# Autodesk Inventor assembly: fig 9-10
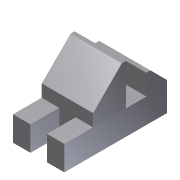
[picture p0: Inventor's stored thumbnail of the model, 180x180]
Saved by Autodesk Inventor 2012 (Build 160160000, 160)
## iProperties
Shininess: 64.0
Length Units: 11269
Angle Units: 11279
Time Units: 11290
Mass Units: 11283
Length Display Precision: 3
Angle Display Precision: 2
Created: 2002-01
Part Number: fig 9-10
Document SubType Name: Assembly
Designer: ***
Density: 0.0
Volumn: 0.0
Area: 0.0
PropertySet Name: Model Information
Control State: 0
Master: False
Checked Out: False
Author: ***
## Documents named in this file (3)
- C:\Users\CadCim\Documents\SAILESH\inventor-2011-fact-prt\c09_inv_2011-prt\c09_inv_2012_prt\fig 9-10.iam
- C:\Users\CadCim\Documents\SAILESH\inventor-2011-fact-prt\c09_inv_2011-prt\c09_inv_2012_prt\Part3.ipt
- C:\Users\CadCim\Documents\SAILESH\inventor-2011-fact-prt\c09_inv_2011-prt\c09_inv_2012_prt\Part4.ipt
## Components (2 placed, 2 different names)
1. Part3:1
2. Part4:1
